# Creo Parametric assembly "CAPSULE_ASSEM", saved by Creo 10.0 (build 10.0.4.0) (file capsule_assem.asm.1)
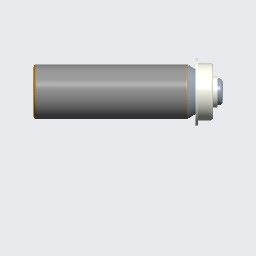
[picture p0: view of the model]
Units: millimeter Kilogram Sec (mmKs); MM, KILOGRAM, SECS

Created from: XX_MMKS_ASM_DESIGN_ABS.ASM

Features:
  1. datum plane "ASM_RIGHT"
  2. datum plane "ASM_TOP"
  3. datum plane "ASM_FRONT"
  4. coordinate system
  5. component "CAPSULE"
  6. component "CAPSULE_TOP"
